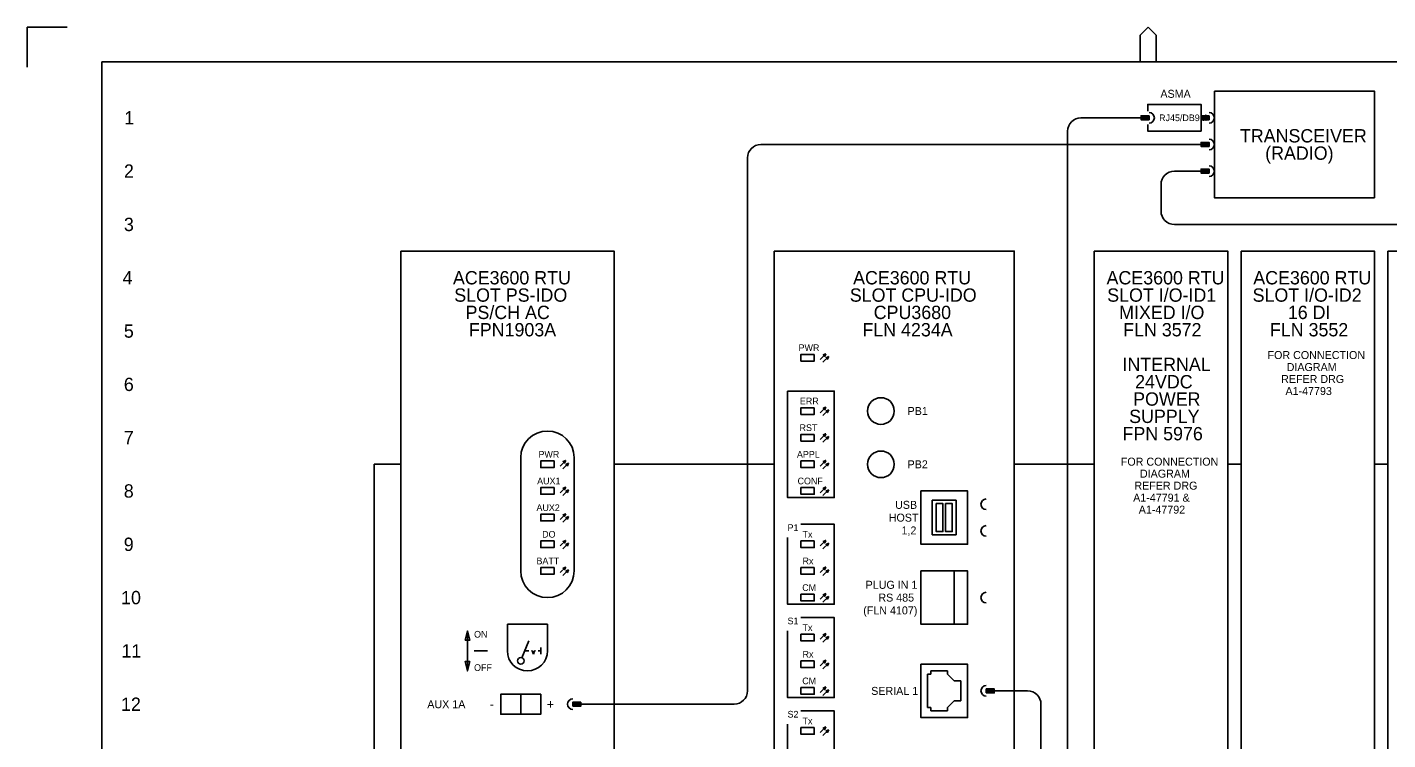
# Model space of a CAD drawing. Extents: x 0 to 841, y 0 to 594.
# Drawn here: x 0 to 510, y 327 to 594 of the extents above; entities that cross this region are included whole.
import ezdxf

# ---------------------------------------------------------------- set-up
doc = ezdxf.new("R2010")
doc.units = 0
for name, color, linetype in [('A1BORDER', 7, 'Continuous'), ('Level 1', 7, 'Continuous'), ('Level 10', 7, 'Continuous')]:
    doc.layers.add(name, color=color, linetype=linetype)

msp = doc.modelspace()

# ---------------------------------------------------------------- linework, layer by layer
at = {"layer": 'A1BORDER'}
for p, q in [((0, 594), (15, 594)), ((0, 579), (0, 594)), ((417.19, 591), (420.19, 594)), ((423.19, 591), (420.19, 594)), ((417.19, 581), (417.19, 591)), ((423.19, 581), (423.19, 591)), ((28, 581), (829, 581)), ((28, 581), (28, 15))]:
    msp.add_line(p, q, dxfattribs=at)
at = {"layer": 'Level 1'}
for p, q in [((417.5, 560), (395, 560)), ((420.5, 560.5), (417.5, 560.5)), ((420.5, 560.25), (417.5, 560.25)), ((420.5, 560), (417.5, 560)), ((420.5, 559.75), (417.5, 559.75)), ((420.5, 559.5), (417.5, 559.5)), ((443, 560.5), (440, 560.5)), ((443, 560.25), (440, 560.25)), ((443, 560), (440, 560)), ((443, 559.75), (440, 559.75)), ((443, 559.5), (440, 559.5)), ((390, 555), (390, 225)), ((440, 550), (275, 550)), ((270, 545), (270, 345)), ((440, 540), (430, 540)), ((425, 535), (425, 525)), ((575, 520), (430, 520)), ((130, 430), (130, 210)), ((130, 430), (140, 430)), ((185, 432.5), (185, 390)), ((205, 432.5), (205, 390)), ((220, 430), (280, 430)), ((370, 430), (400, 430)), ((450, 430), (455, 430)), ((505, 430), (510, 430)), ((339.25, 416.5), (339.25, 403.5)), ((339.25, 416.5), (348.25, 416.5)), ((348.25, 416.5), (348.25, 403.5)), ((339.25, 403.5), (348.25, 403.5)), ((347.5, 390), (347.5, 370)), ((165, 367.5), (165, 357.5)), ((180, 370), (195, 370)), ((180, 360), (180, 370)), ((195, 360), (195, 370)), ((165, 352.5), (165, 362.5)), ((167.5, 360), (172.5, 360)), ((345, 352.5), (338.75, 352.5)), ((338.75, 352.5), (338.75, 351.25)), ((345, 351.25), (345, 352.5)), ((337.5, 351.25), (337.5, 338.75)), ((338.75, 351.25), (337.5, 351.25)), ((345, 351.25), (347.5, 348.75)), ((350, 348.75), (347.5, 348.75)), ((350, 341.25), (350, 348.75)), ((185, 343.75), (185, 336.25)), ((362.5, 345), (375, 345)), ((207.5, 340), (265, 340)), ((337.5, 338.75), (338.75, 338.75)), ((338.75, 338.75), (338.75, 337.5)), ((338.75, 337.5), (345, 337.5)), ((345, 338.75), (347.5, 341.25)), ((345, 337.5), (345, 338.75)), ((347.5, 341.25), (350, 341.25)), ((380, 340), (380, 155))]:
    msp.add_line(p, q, dxfattribs=at)
for points in [[(445, 570), (505, 570), (505, 530), (445, 530)], [(140, 510), (220, 510), (220, 160), (140, 160)], [(280, 510), (370, 510), (370, 160), (280, 160)], [(400, 510), (450, 510), (450, 160), (400, 160)], [(455, 510), (505, 510), (505, 160), (455, 160)], [(510, 510), (560, 510), (560, 160), (510, 160)], [(295, 471.25), (290, 471.25), (290, 468.75), (295, 468.75)], [(285, 457.5), (302.5, 457.5), (302.5, 417.5), (285, 417.5)], [(295, 451.25), (290, 451.25), (290, 448.75), (295, 448.75)], [(295, 441.25), (290, 441.25), (290, 438.75), (295, 438.75)], [(197.5, 431.25), (192.5, 431.25), (192.5, 428.75), (197.5, 428.75)], [(295, 431.25), (290, 431.25), (290, 428.75), (295, 428.75)], [(197.5, 421.25), (192.5, 421.25), (192.5, 418.75), (197.5, 418.75)], [(295, 421.25), (290, 421.25), (290, 418.75), (295, 418.75)], [(335, 420), (352.5, 420), (352.5, 400), (335, 400)], [(340.75, 415.25), (343.25, 415.25), (343.25, 404.75), (340.75, 404.75)], [(344.25, 415.25), (346.75, 415.25), (346.75, 404.75), (344.25, 404.75)], [(197.5, 411.25), (192.5, 411.25), (192.5, 408.75), (197.5, 408.75)], [(197.5, 401.25), (192.5, 401.25), (192.5, 398.75), (197.5, 398.75)], [(295, 401.25), (290, 401.25), (290, 398.75), (295, 398.75)], [(197.5, 391.25), (192.5, 391.25), (192.5, 388.75), (197.5, 388.75)], [(295, 391.25), (290, 391.25), (290, 388.75), (295, 388.75)], [(335, 390), (352.5, 390), (352.5, 370), (335, 370)], [(295, 381.25), (290, 381.25), (290, 378.75), (295, 378.75)], [(164.13, 364), (165, 367.5), (165.87, 364)], [(295, 366.25), (290, 366.25), (290, 363.75), (295, 363.75)], [(165.87, 356), (165, 352.5), (164.13, 356)], [(295, 356.25), (290, 356.25), (290, 353.75), (295, 353.75)], [(335, 355), (352.5, 355), (352.5, 335), (335, 335)], [(192.5, 343.75), (177.5, 343.75), (177.5, 336.25), (192.5, 336.25)], [(295, 346.25), (290, 346.25), (290, 343.75), (295, 343.75)], [(295, 331.25), (290, 331.25), (290, 328.75), (295, 328.75)]]:
    msp.add_lwpolyline(points, close=True, dxfattribs=at)
for points in [[(420, 562.5), (420, 565), (440, 565), (440, 555), (420, 555), (420, 557.5)], [(290, 407.5), (302.5, 407.5), (302.5, 377.5), (285, 377.5), (285, 402.5)], [(290, 372.5), (302.5, 372.5), (302.5, 342.5), (285, 342.5), (285, 367.5)], [(290, 337.5), (302.5, 337.5), (302.5, 307.5), (285, 307.5), (285, 332.5)]]:
    msp.add_lwpolyline(points, dxfattribs=at)
for centre in [(320, 450), (320, 430)]:
    msp.add_circle(centre, 5, dxfattribs=at)
for centre, radius, start, end in [((395, 555), 5, 90, 180), ((275, 545), 5, 90, 180), ((430, 535), 5, 90, 180), ((430, 525), 5, 180, 270), ((195, 432.5), 10, 0, 180), ((195, 390), 10, 180, 0), ((187.5, 360), 7.5, 180, 0), ((265, 345), 5, 270, 360), ((375, 340), 5, 0, 90)]:
    msp.add_arc(centre, radius, start, end, dxfattribs=at)
at = {"layer": 'Level 10'}
for p, q in [((443, 550.48), (440, 550.48)), ((443, 550.18), (440, 550.18)), ((443, 549.88), (440, 549.88)), ((443, 549.58), (440, 549.58)), ((443, 549.28), (440, 549.28)), ((443, 540.48), (440, 540.48)), ((443, 540.18), (440, 540.18)), ((443, 539.88), (440, 539.88)), ((443, 539.58), (440, 539.58)), ((443, 539.28), (440, 539.28)), ((297.23, 469.36), (299.36, 471.48)), ((298.29, 468.3), (300.42, 470.42)), ((298.46, 471.07), (299.17, 471.07)), ((298.5, 470.93), (299.11, 470.93)), ((298.64, 470.78), (299.04, 470.78)), ((298.79, 471.23), (299.24, 471.23)), ((298.8, 470.62), (298.97, 470.62)), ((299.12, 471.38), (299.31, 471.38)), ((299.52, 470.01), (300.23, 470.01)), ((299.56, 469.87), (300.17, 469.87)), ((299.7, 469.72), (300.1, 469.72)), ((299.85, 470.17), (300.3, 470.17)), ((299.86, 469.56), (300.03, 469.56)), ((300.18, 470.31), (300.37, 470.31)), ((297.23, 449.36), (299.36, 451.48)), ((298.29, 448.3), (300.42, 450.42)), ((298.46, 451.07), (299.17, 451.07)), ((298.5, 450.93), (299.11, 450.93)), ((298.64, 450.78), (299.04, 450.78)), ((298.79, 451.23), (299.24, 451.23)), ((298.8, 450.62), (298.97, 450.62)), ((299.12, 451.38), (299.31, 451.38)), ((299.52, 450.01), (300.23, 450.01)), ((299.56, 449.87), (300.17, 449.87)), ((299.7, 449.72), (300.1, 449.72)), ((299.85, 450.17), (300.3, 450.17)), ((299.86, 449.56), (300.03, 449.56)), ((300.18, 450.31), (300.37, 450.31)), ((297.23, 439.36), (299.36, 441.48)), ((298.29, 438.3), (300.42, 440.42)), ((298.46, 441.07), (299.17, 441.07)), ((298.5, 440.93), (299.11, 440.93)), ((298.64, 440.78), (299.04, 440.78)), ((298.79, 441.23), (299.24, 441.23)), ((298.8, 440.62), (298.97, 440.62)), ((299.12, 441.38), (299.31, 441.38)), ((299.52, 440.01), (300.23, 440.01)), ((299.56, 439.87), (300.17, 439.87)), ((299.7, 439.72), (300.1, 439.72)), ((299.85, 440.17), (300.3, 440.17)), ((299.86, 439.56), (300.03, 439.56)), ((300.18, 440.31), (300.37, 440.31)), ((199.73, 429.36), (201.86, 431.48)), ((200.79, 428.3), (202.91, 430.42)), ((200.96, 431.07), (201.67, 431.07)), ((201, 430.93), (201.61, 430.93)), ((201.15, 430.78), (201.53, 430.78)), ((201.29, 431.23), (201.74, 431.23)), ((201.3, 430.62), (201.47, 430.62)), ((201.62, 431.38), (201.81, 431.38)), ((202.02, 430.01), (202.73, 430.01)), ((202.06, 429.87), (202.66, 429.87)), ((202.21, 429.72), (202.59, 429.72)), ((202.35, 430.17), (202.8, 430.17)), ((202.36, 429.56), (202.53, 429.56)), ((202.68, 430.31), (202.87, 430.31)), ((297.23, 429.36), (299.36, 431.48)), ((298.29, 428.3), (300.42, 430.42)), ((298.46, 431.07), (299.17, 431.07)), ((298.5, 430.93), (299.11, 430.93)), ((298.64, 430.78), (299.04, 430.78)), ((298.79, 431.23), (299.24, 431.23)), ((298.8, 430.62), (298.97, 430.62)), ((299.12, 431.38), (299.31, 431.38)), ((299.52, 430.01), (300.23, 430.01)), ((299.56, 429.87), (300.17, 429.87)), ((299.7, 429.72), (300.1, 429.72)), ((299.85, 430.17), (300.3, 430.17)), ((299.86, 429.56), (300.03, 429.56)), ((300.18, 430.31), (300.37, 430.31)), ((199.73, 419.36), (201.86, 421.48)), ((200.79, 418.3), (202.91, 420.42)), ((200.96, 421.07), (201.67, 421.07)), ((201, 420.93), (201.61, 420.93)), ((201.15, 420.78), (201.53, 420.78)), ((201.29, 421.23), (201.74, 421.23)), ((201.3, 420.62), (201.47, 420.62)), ((201.62, 421.38), (201.81, 421.38)), ((202.02, 420.01), (202.73, 420.01)), ((202.06, 419.87), (202.66, 419.87)), ((202.21, 419.72), (202.59, 419.72)), ((202.35, 420.17), (202.8, 420.17)), ((202.36, 419.56), (202.53, 419.56)), ((202.68, 420.31), (202.87, 420.31)), ((297.23, 419.36), (299.36, 421.48)), ((298.29, 418.3), (300.42, 420.42)), ((298.46, 421.07), (299.17, 421.07)), ((298.5, 420.93), (299.11, 420.93)), ((298.64, 420.78), (299.04, 420.78)), ((298.79, 421.23), (299.24, 421.23)), ((298.8, 420.62), (298.97, 420.62)), ((299.12, 421.38), (299.31, 421.38)), ((299.52, 420.01), (300.23, 420.01)), ((299.56, 419.87), (300.17, 419.87)), ((299.7, 419.72), (300.1, 419.72)), ((299.85, 420.17), (300.3, 420.17)), ((299.86, 419.56), (300.03, 419.56)), ((300.18, 420.31), (300.37, 420.31)), ((199.73, 409.36), (201.86, 411.48)), ((200.79, 408.3), (202.91, 410.42)), ((200.96, 411.07), (201.67, 411.07)), ((201, 410.93), (201.61, 410.93)), ((201.15, 410.78), (201.53, 410.78)), ((201.29, 411.23), (201.74, 411.23)), ((201.3, 410.62), (201.47, 410.62)), ((201.62, 411.38), (201.81, 411.38)), ((202.02, 410.01), (202.73, 410.01)), ((202.06, 409.87), (202.66, 409.87)), ((202.21, 409.72), (202.59, 409.72)), ((202.35, 410.17), (202.8, 410.17)), ((202.36, 409.56), (202.53, 409.56)), ((202.68, 410.31), (202.87, 410.31)), ((199.73, 399.36), (201.86, 401.48)), ((200.79, 398.3), (202.91, 400.42)), ((200.96, 401.07), (201.67, 401.07)), ((201, 400.93), (201.61, 400.93)), ((201.15, 400.78), (201.53, 400.78)), ((201.29, 401.23), (201.74, 401.23)), ((201.3, 400.62), (201.47, 400.62)), ((201.62, 401.38), (201.81, 401.38)), ((202.02, 400.01), (202.73, 400.01)), ((202.06, 399.87), (202.66, 399.87)), ((202.21, 399.72), (202.59, 399.72)), ((202.35, 400.17), (202.8, 400.17)), ((202.36, 399.56), (202.53, 399.56)), ((202.68, 400.31), (202.87, 400.31)), ((297.23, 399.36), (299.36, 401.48)), ((298.29, 398.3), (300.42, 400.42)), ((298.46, 401.07), (299.17, 401.07)), ((298.5, 400.93), (299.11, 400.93)), ((298.64, 400.78), (299.04, 400.78)), ((298.79, 401.23), (299.24, 401.23)), ((298.8, 400.62), (298.97, 400.62)), ((299.12, 401.38), (299.31, 401.38)), ((299.52, 400.01), (300.23, 400.01)), ((299.56, 399.87), (300.17, 399.87)), ((299.7, 399.72), (300.1, 399.72)), ((299.85, 400.17), (300.3, 400.17)), ((299.86, 399.56), (300.03, 399.56)), ((300.18, 400.31), (300.37, 400.31)), ((199.73, 389.36), (201.86, 391.48)), ((200.79, 388.3), (202.91, 390.42)), ((200.96, 391.07), (201.67, 391.07)), ((201, 390.93), (201.61, 390.93)), ((201.15, 390.78), (201.53, 390.78)), ((201.29, 391.23), (201.74, 391.23)), ((201.3, 390.62), (201.47, 390.62)), ((201.62, 391.38), (201.81, 391.38)), ((202.02, 390.01), (202.73, 390.01)), ((202.06, 389.87), (202.66, 389.87)), ((202.21, 389.72), (202.59, 389.72)), ((202.35, 390.17), (202.8, 390.17)), ((202.36, 389.56), (202.53, 389.56)), ((202.68, 390.31), (202.87, 390.31)), ((297.23, 389.36), (299.36, 391.48)), ((298.29, 388.3), (300.42, 390.42)), ((298.46, 391.07), (299.17, 391.07)), ((298.5, 390.93), (299.11, 390.93)), ((298.64, 390.78), (299.04, 390.78)), ((298.79, 391.23), (299.24, 391.23)), ((298.8, 390.62), (298.97, 390.62)), ((299.12, 391.38), (299.31, 391.38)), ((299.52, 390.01), (300.23, 390.01)), ((299.56, 389.87), (300.17, 389.87)), ((299.7, 389.72), (300.1, 389.72)), ((299.85, 390.17), (300.3, 390.17)), ((299.86, 389.56), (300.03, 389.56)), ((300.18, 390.31), (300.37, 390.31)), ((297.23, 379.36), (299.36, 381.48)), ((298.29, 378.3), (300.42, 380.42)), ((298.46, 381.07), (299.17, 381.07)), ((298.5, 380.93), (299.11, 380.93)), ((298.64, 380.78), (299.04, 380.78)), ((298.79, 381.23), (299.24, 381.23)), ((298.8, 380.62), (298.97, 380.62)), ((299.12, 381.38), (299.31, 381.38)), ((299.52, 380.01), (300.23, 380.01)), ((299.56, 379.87), (300.17, 379.87)), ((299.7, 379.72), (300.1, 379.72)), ((299.85, 380.17), (300.3, 380.17)), ((299.86, 379.56), (300.03, 379.56)), ((300.18, 380.31), (300.37, 380.31)), ((185.46, 357.41), (188, 363.75)), ((297.23, 364.36), (299.36, 366.48)), ((298.29, 363.3), (300.42, 365.42)), ((298.46, 366.07), (299.17, 366.07)), ((298.5, 365.93), (299.11, 365.93)), ((298.64, 365.78), (299.04, 365.78)), ((298.79, 366.23), (299.24, 366.23)), ((298.8, 365.62), (298.97, 365.62)), ((299.12, 366.38), (299.31, 366.38)), ((299.52, 365.01), (300.23, 365.01)), ((299.56, 364.87), (300.17, 364.87)), ((299.7, 364.72), (300.1, 364.72)), ((299.85, 365.17), (300.3, 365.17)), ((299.86, 364.56), (300.03, 364.56)), ((300.18, 365.31), (300.37, 365.31)), ((186.5, 360), (188, 360)), ((189, 360), (189.33, 360)), ((189.75, 358.75), (189.33, 360)), ((189.75, 358.75), (190.17, 360)), ((190.5, 360), (190.17, 360)), ((191.5, 360), (192.5, 360)), ((192.5, 358.75), (192.5, 361.25)), ((297.23, 354.36), (299.36, 356.48)), ((298.29, 353.3), (300.42, 355.42)), ((298.46, 356.07), (299.17, 356.07)), ((298.5, 355.93), (299.11, 355.93)), ((298.64, 355.78), (299.04, 355.78)), ((298.79, 356.23), (299.24, 356.23)), ((298.8, 355.62), (298.97, 355.62)), ((299.12, 356.38), (299.31, 356.38)), ((299.52, 355.01), (300.23, 355.01)), ((299.56, 354.87), (300.17, 354.87)), ((299.7, 354.72), (300.1, 354.72)), ((299.85, 355.17), (300.3, 355.17)), ((299.86, 354.56), (300.03, 354.56)), ((300.18, 355.31), (300.37, 355.31)), ((297.23, 344.36), (299.36, 346.48)), ((298.29, 343.3), (300.42, 345.42)), ((298.46, 346.07), (299.17, 346.07)), ((298.5, 345.93), (299.11, 345.93)), ((298.64, 345.78), (299.04, 345.78)), ((298.79, 346.23), (299.24, 346.23)), ((298.8, 345.62), (298.97, 345.62)), ((299.12, 346.38), (299.31, 346.38)), ((299.52, 345.01), (300.23, 345.01)), ((299.56, 344.87), (300.17, 344.87)), ((299.7, 344.72), (300.1, 344.72)), ((299.85, 345.17), (300.3, 345.17)), ((299.86, 344.56), (300.03, 344.56)), ((300.18, 345.31), (300.37, 345.31)), ((359.5, 345.5), (362.5, 345.5)), ((359.5, 345.25), (362.5, 345.25)), ((359.5, 345), (362.5, 345)), ((359.5, 344.75), (362.5, 344.75)), ((359.5, 344.5), (362.5, 344.5)), ((204.5, 340.48), (207.5, 340.48)), ((204.5, 340.18), (207.5, 340.18)), ((204.5, 339.88), (207.5, 339.88)), ((204.5, 339.58), (207.5, 339.58)), ((204.5, 339.28), (207.5, 339.28)), ((297.23, 329.36), (299.36, 331.48)), ((298.29, 328.3), (300.42, 330.42)), ((298.46, 331.07), (299.17, 331.07)), ((298.5, 330.93), (299.11, 330.93)), ((298.64, 330.78), (299.04, 330.78)), ((298.79, 331.23), (299.24, 331.23)), ((298.8, 330.62), (298.97, 330.62)), ((299.12, 331.38), (299.31, 331.38)), ((299.52, 330.01), (300.23, 330.01)), ((299.56, 329.87), (300.17, 329.87)), ((299.7, 329.72), (300.1, 329.72)), ((299.85, 330.17), (300.3, 330.17)), ((299.86, 329.56), (300.03, 329.56)), ((300.18, 330.31), (300.37, 330.31))]:
    msp.add_line(p, q, dxfattribs=at)
for points in [[(420.5, 560.75), (417.5, 560.75), (417.5, 559.25), (420.5, 559.25)], [(443, 560.75), (440, 560.75), (440, 559.25), (443, 559.25)], [(443, 549.25), (440, 549.25), (440, 550.75), (443, 550.75)], [(443, 539.25), (440, 539.25), (440, 540.75), (443, 540.75)], [(299.36, 471.48), (298.38, 471.04), (298.92, 470.5)], [(300.42, 470.42), (299.44, 469.98), (299.98, 469.44)], [(299.36, 451.48), (298.38, 451.04), (298.92, 450.5)], [(300.42, 450.42), (299.44, 449.98), (299.98, 449.44)], [(299.36, 441.48), (298.38, 441.04), (298.92, 440.5)], [(300.42, 440.42), (299.44, 439.98), (299.98, 439.44)], [(201.86, 431.48), (200.88, 431.04), (201.41, 430.5)], [(202.91, 430.42), (201.94, 429.98), (202.47, 429.44)], [(299.36, 431.48), (298.38, 431.04), (298.92, 430.5)], [(300.42, 430.42), (299.44, 429.98), (299.98, 429.44)], [(201.86, 421.48), (200.88, 421.04), (201.41, 420.5)], [(202.91, 420.42), (201.94, 419.98), (202.47, 419.44)], [(299.36, 421.48), (298.38, 421.04), (298.92, 420.5)], [(300.42, 420.42), (299.44, 419.98), (299.98, 419.44)], [(201.86, 411.48), (200.88, 411.04), (201.41, 410.5)], [(202.91, 410.42), (201.94, 409.98), (202.47, 409.44)], [(201.86, 401.48), (200.88, 401.04), (201.41, 400.5)], [(202.91, 400.42), (201.94, 399.98), (202.47, 399.44)], [(299.36, 401.48), (298.38, 401.04), (298.92, 400.5)], [(300.42, 400.42), (299.44, 399.98), (299.98, 399.44)], [(201.86, 391.48), (200.88, 391.04), (201.41, 390.5)], [(202.91, 390.42), (201.94, 389.98), (202.47, 389.44)], [(299.36, 391.48), (298.38, 391.04), (298.92, 390.5)], [(300.42, 390.42), (299.44, 389.98), (299.98, 389.44)], [(299.36, 381.48), (298.38, 381.04), (298.92, 380.5)], [(300.42, 380.42), (299.44, 379.98), (299.98, 379.44)], [(299.36, 366.48), (298.38, 366.04), (298.92, 365.5)], [(300.42, 365.42), (299.44, 364.98), (299.98, 364.44)], [(299.36, 356.48), (298.38, 356.04), (298.92, 355.5)], [(300.42, 355.42), (299.44, 354.98), (299.98, 354.44)], [(299.36, 346.48), (298.38, 346.04), (298.92, 345.5)], [(300.42, 345.42), (299.44, 344.98), (299.98, 344.44)], [(359.5, 344.25), (362.5, 344.25), (362.5, 345.75), (359.5, 345.75)], [(204.5, 339.25), (207.5, 339.25), (207.5, 340.75), (204.5, 340.75)], [(299.36, 331.48), (298.38, 331.04), (298.92, 330.5)], [(300.42, 330.42), (299.44, 329.98), (299.98, 329.44)]]:
    msp.add_lwpolyline(points, close=True, dxfattribs=at)
msp.add_circle((185, 356.25), 1.25, dxfattribs=at)
for centre, start, end in [((420.5, 560), 270, 90), ((443, 560), 270, 90), ((443, 550), 270, 90), ((443, 540), 270, 90), ((359.5, 415), 90, 270), ((359.5, 405), 90, 270), ((359.5, 380), 90, 270), ((359.5, 345), 90, 270), ((204.5, 340), 90, 270)]:
    msp.add_arc(centre, 2, start, end, dxfattribs=at)

# ---------------------------------------------------------------- texts
at = {"layer": 'Level 1'}
for s, height, p in [('ASMA', 3, (424.77, 567.5)), ('1', 5, (36.41, 557.5)), ('RJ45/DB9M', 2.5, (424.28, 558.75)), ('TRANSCEIVER', 5, (454.58, 550.75)), ('(RADIO)', 5, (464.04, 544.25)), ('2', 5, (36.26, 537.5)), ('3', 5, (36.25, 517.5)), ('4', 5, (35.73, 497.5)), ('ACE3600 RTU', 5, (159.58, 497.5)), ('ACE3600 RTU', 5, (309.58, 497.5)), ('ACE3600 RTU', 5, (404.58, 497.5)), ('ACE3600 RTU', 5, (459.58, 497.5)), ('SLOT PS-IDO', 5, (160.08, 491)), ('SLOT CPU-IDO', 5, (308.34, 491)), ('SLOT I/O-ID1', 5, (404.83, 491)), ('SLOT I/O-ID2', 5, (459.33, 491)), ('PS/CH AC', 5, (164.31, 484.5)), ('MIXED I/O', 5, (409.31, 484.5)), ('CPU3680', 5, (317.3, 484.5)), ('16 DI', 5, (472.53, 484.5)), ('5', 5, (36.23, 477.5)), ('FPN1903A', 5, (165.56, 478)), ('FLN 4234A', 5, (313.07, 478)), ('FLN 3572', 5, (410.81, 478)), ('FLN 3552', 5, (465.81, 478)), ('PWR', 2.5, (289.14, 472.5)), ('INTERNAL', 5, (410.56, 465)), ('FOR CONNECTION', 3, (464.93, 469.5)), ('DIAGRAM', 3, (472.1, 465)), ('6', 5, (36.22, 457.5)), ('24VDC', 5, (415.29, 458.5)), ('REFER DRG', 3, (470.01, 460.5)), ('A1-47793', 3, (471.65, 456)), ('ERR', 2.5, (289.64, 452.5)), ('POWER', 5, (414.54, 452)), ('PB1', 3, (330, 448.5)), ('SUPPLY', 5, (413.05, 445.5)), ('RST', 2.5, (289.51, 442.5)), ('FPN 5976', 5, (410.56, 439)), ('7', 5, (36.21, 437.5)), ('PWR', 2.5, (191.64, 432.5)), ('APPL', 2.5, (288.52, 432.5)), ('PB2', 3, (330, 428.5)), ('FOR CONNECTION', 3, (409.93, 429.5)), ('AUX1', 2.5, (191.14, 422.5)), ('CONF', 2.5, (288.76, 422.5)), ('REFER DRG', 3, (415.01, 420.5)), ('DIAGRAM', 3, (417.1, 425)), ('8', 5, (36.2, 417.5)), ('A1-47791 &', 3, (414.56, 416)), ('AUX2', 2.5, (190.89, 412.5)), ('USB', 3, (325.33, 413.3)), ('A1-47792', 3, (416.65, 411.5)), ('HOST', 3, (322.94, 408.5)), ('DO', 2.5, (193.01, 402.5)), ('P1', 2.5, (285, 405)), ('Tx', 2.5, (290.63, 402.5)), ('1,2', 3, (327.72, 403.7)), ('9', 5, (36.19, 397.5)), ('BATT', 2.5, (190.89, 392.5)), ('Rx', 2.5, (290.63, 392.5)), ('10', 5, (35.19, 377.5)), ('CM', 2.5, (290.51, 382.5)), ('PLUG IN 1', 3, (314.27, 383.3)), ('RS 485', 3, (319.05, 378.5)), ('S1', 2.5, (285, 370)), ('(FLN 4107)', 3, (313.38, 373.7)), ('ON', 2.5, (167.5, 365)), ('Tx', 2.5, (290.63, 367.5)), ('11', 5, (35.33, 357.5)), ('Rx', 2.5, (290.63, 357.5)), ('OFF', 2.5, (167.5, 352.5)), ('CM', 2.5, (290.51, 347.5)), ('12', 5, (35.17, 337.5)), ('SERIAL 1', 3, (316.36, 343.5)), ('AUX 1A', 3, (149.97, 338.5)), ('-', 3.5, (173.4, 338.25)), ('+', 3.5, (194.75, 338.25)), ('S2', 2.5, (285, 335)), ('Tx', 2.5, (290.63, 332.5))]:
    msp.add_text(s, height=height, dxfattribs=at).set_placement(p)

doc.saveas('drawing.dxf')
